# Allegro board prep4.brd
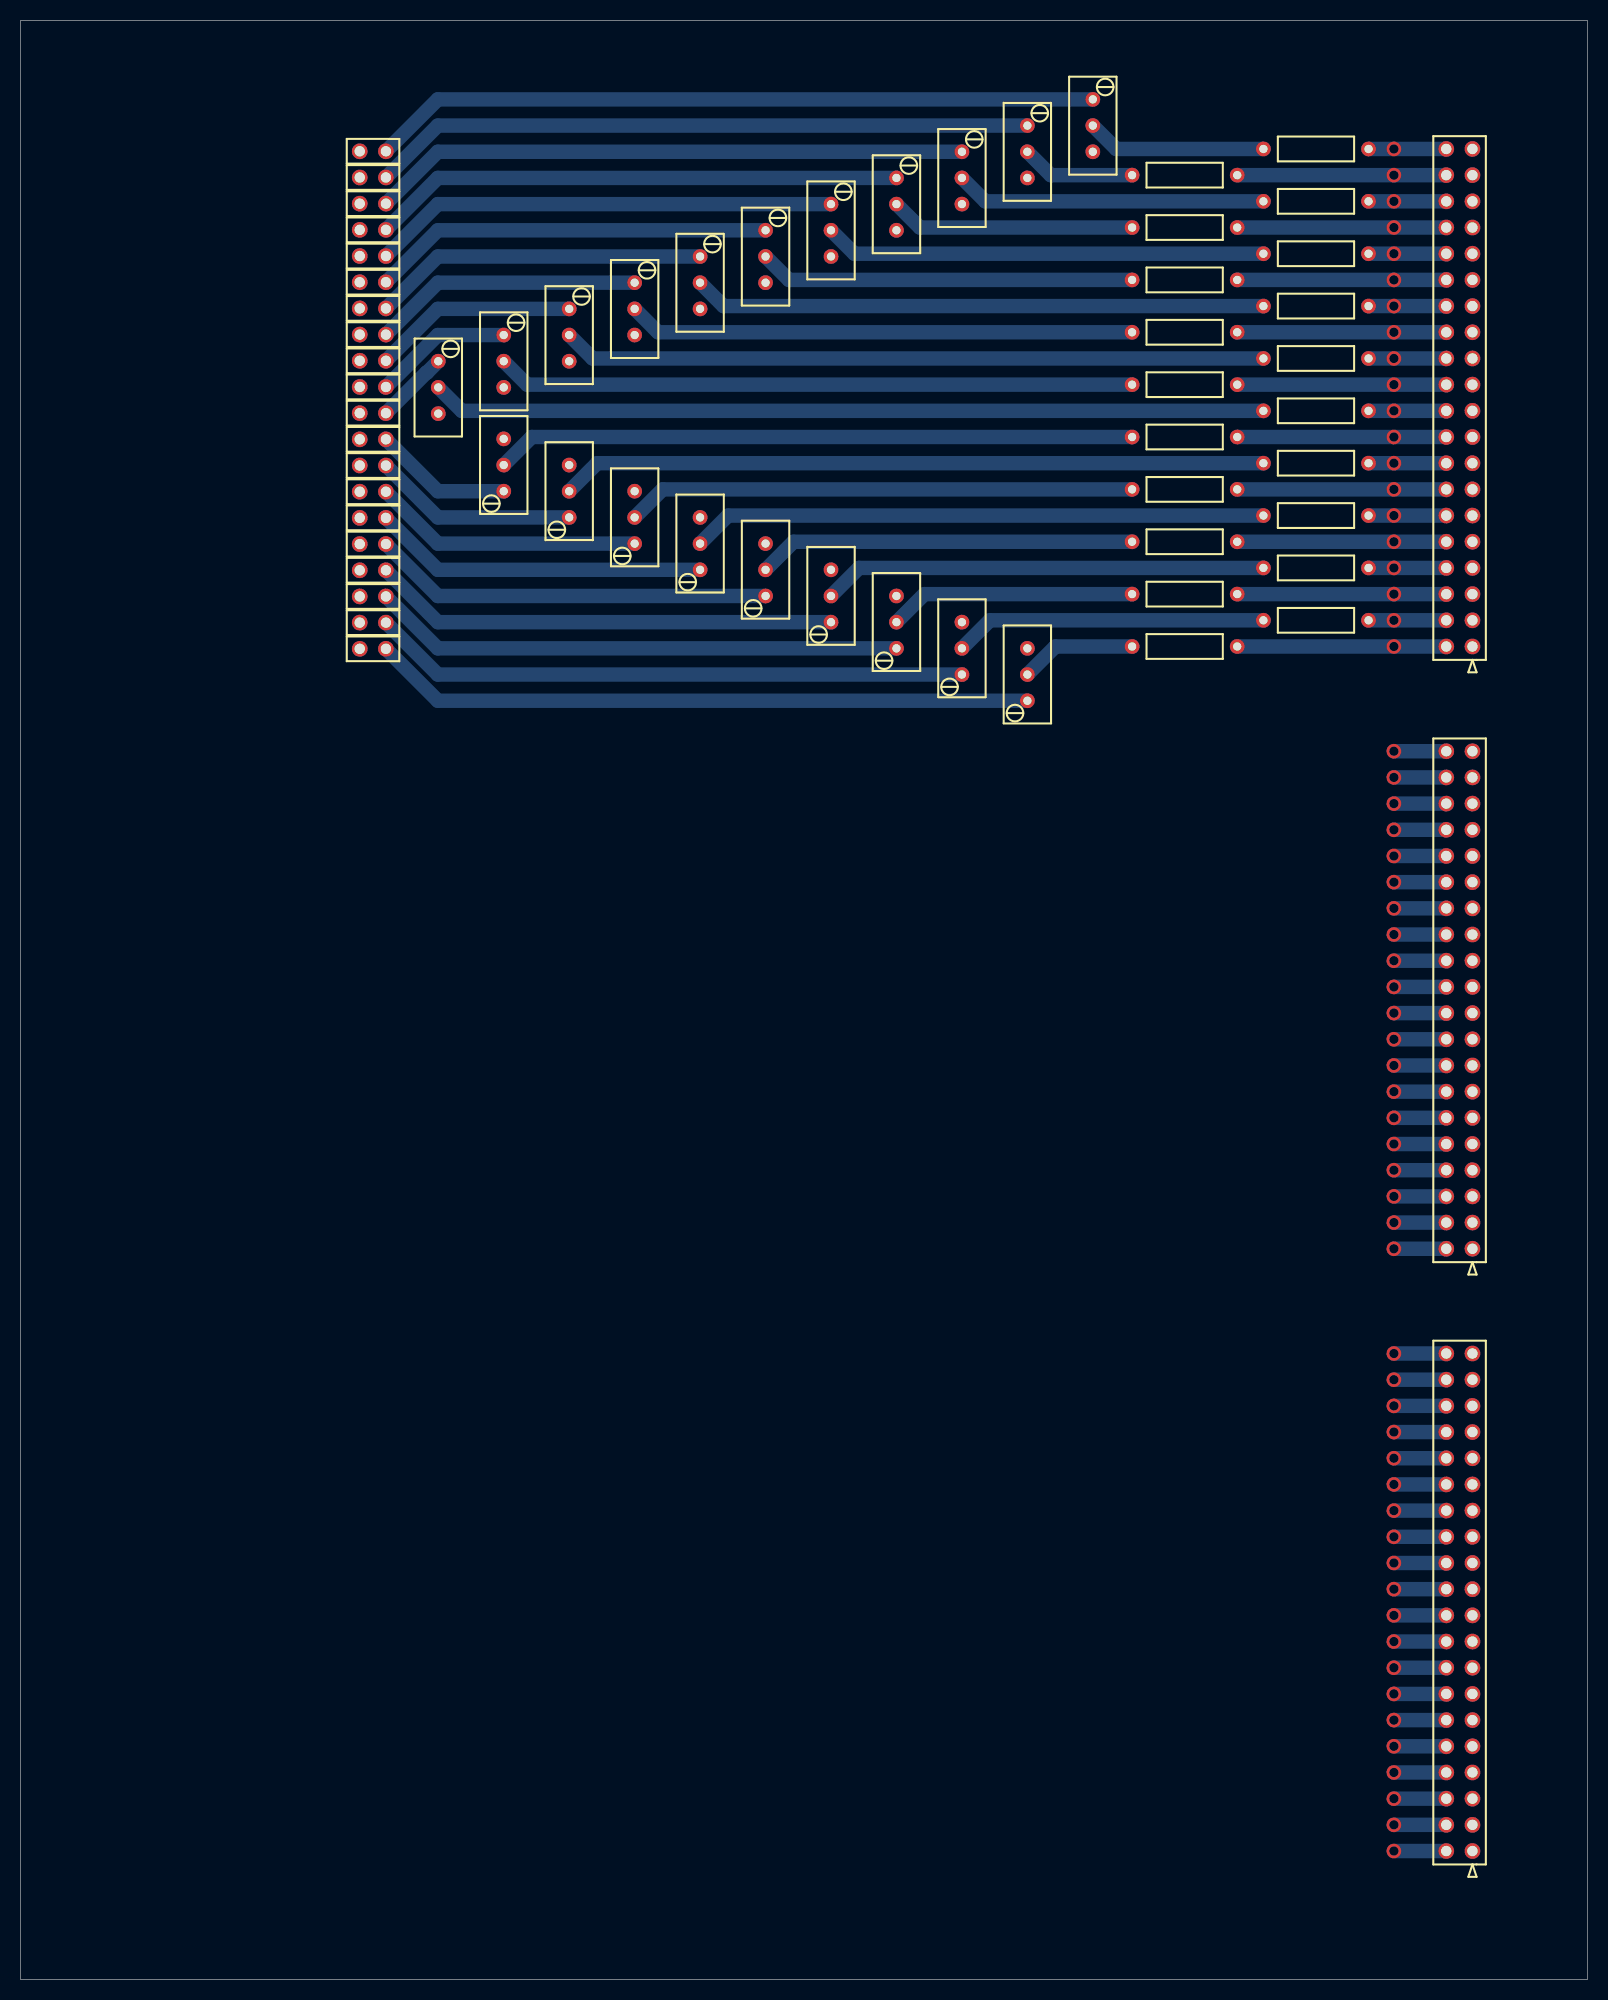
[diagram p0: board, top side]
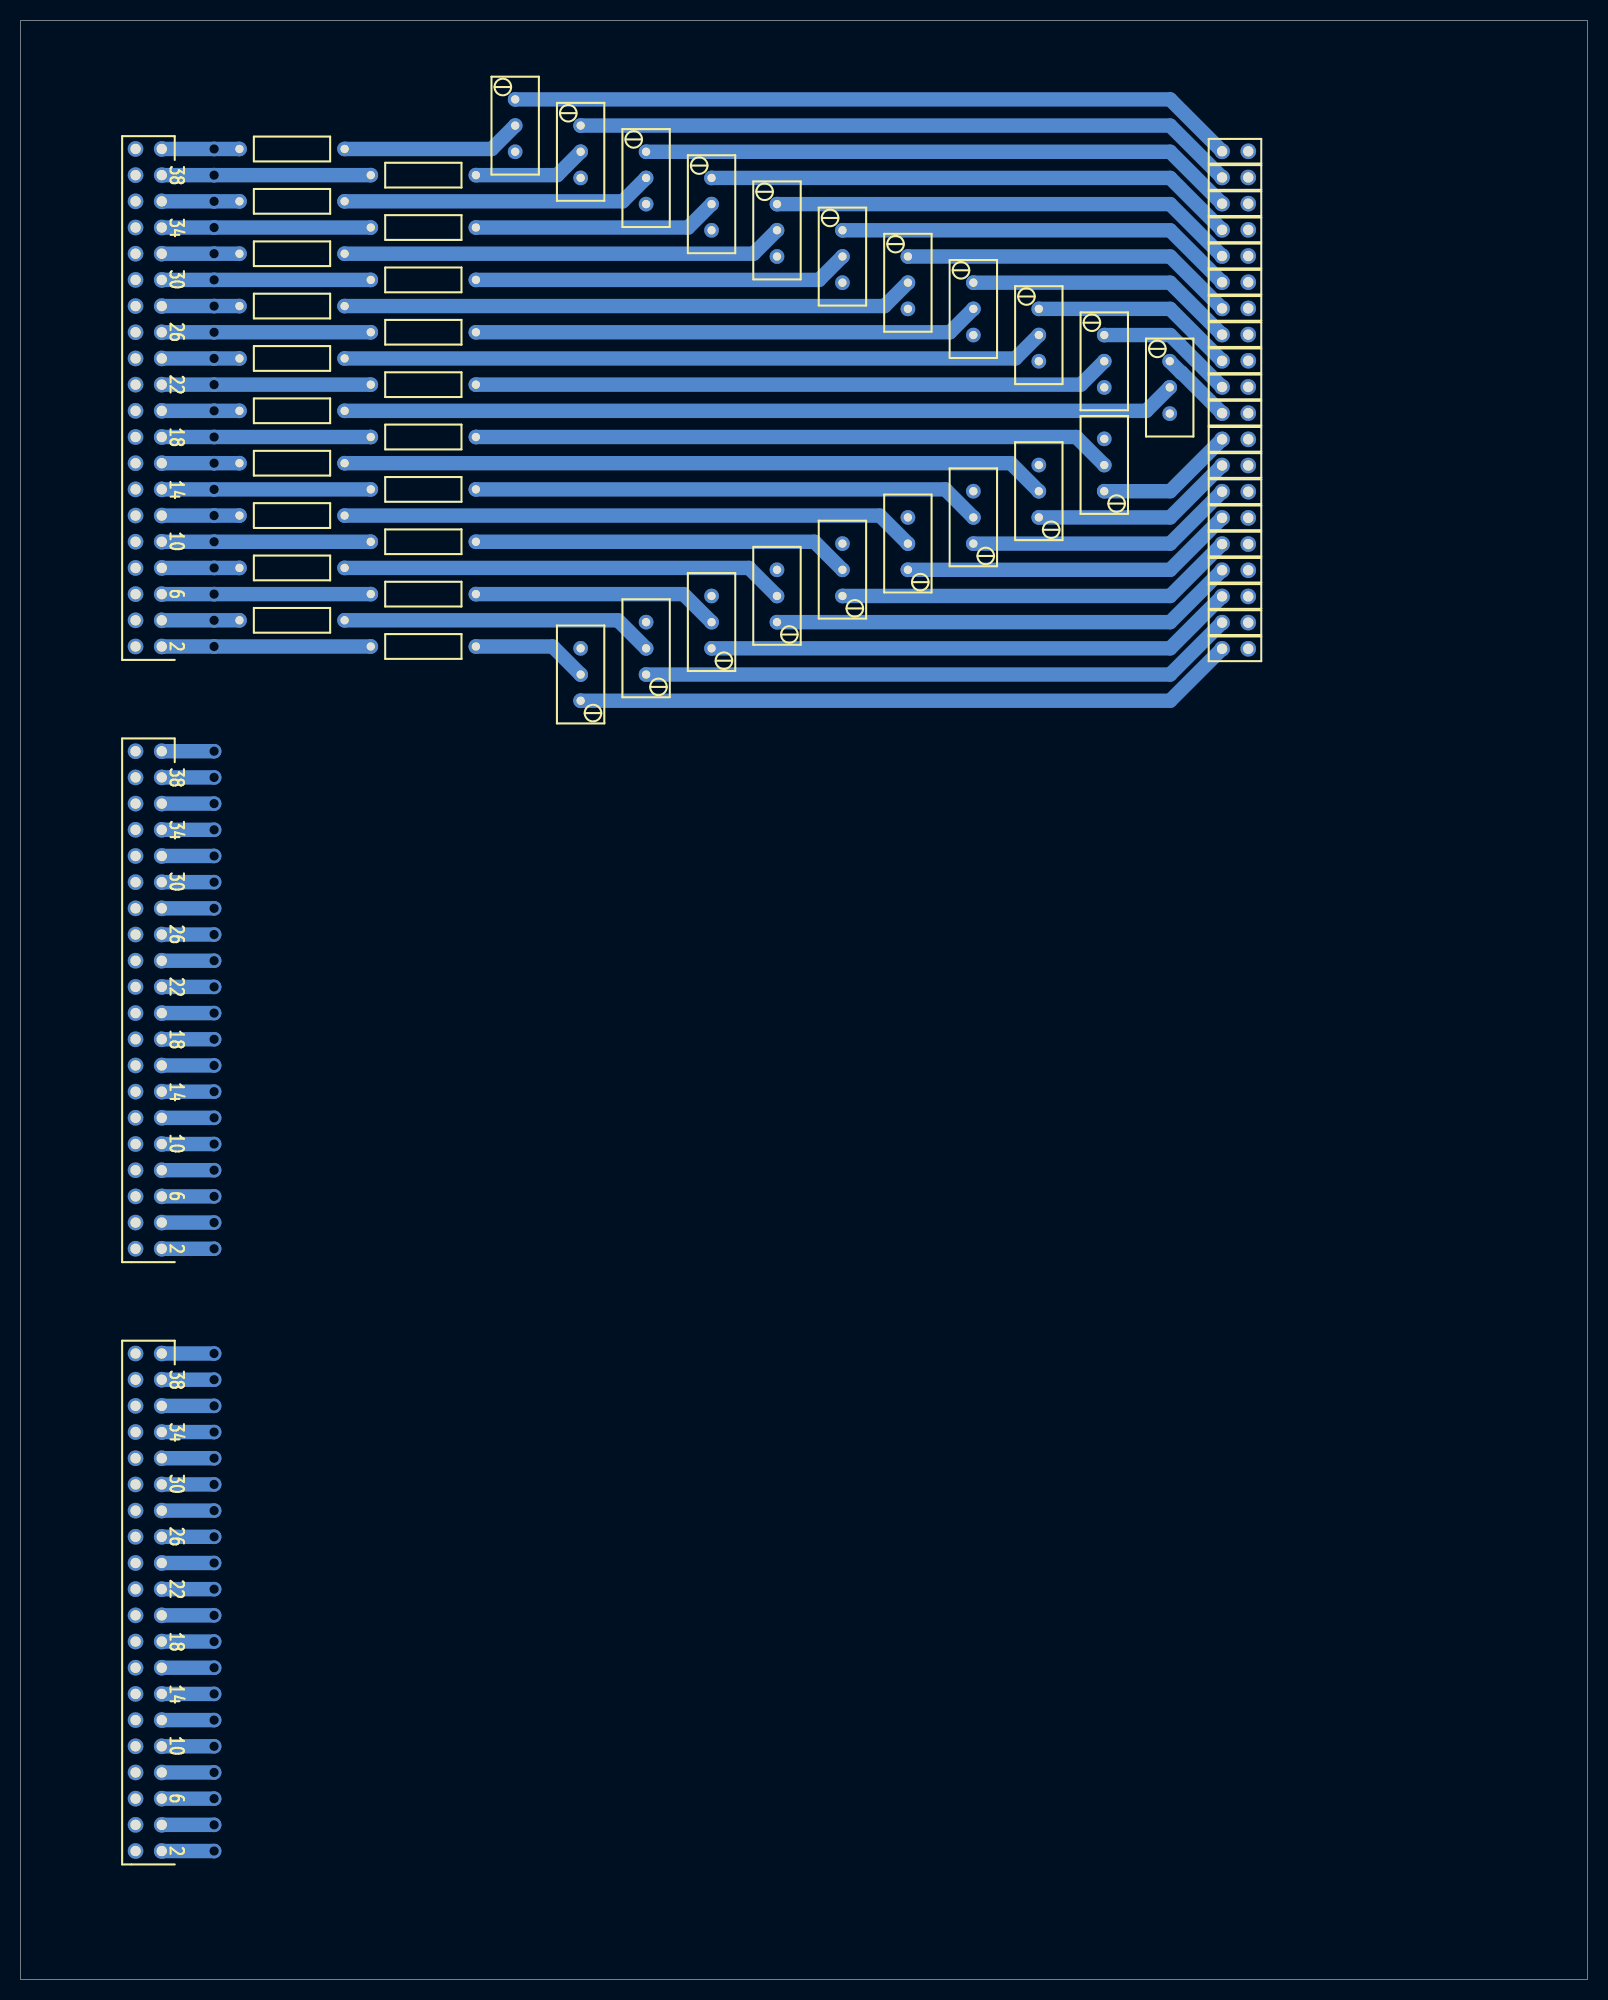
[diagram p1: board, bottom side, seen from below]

Outline 152 x 190 mm; copper layers: TOP, BOTTOM. Coordinates in mm from the lower left corner of the outline.
Outline path: 0,190 152,190 152,0 0,0 0,190

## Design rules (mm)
constraint set DEFAULT: min track width 0.15, pair gap 0.15

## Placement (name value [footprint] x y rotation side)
J1  -  [CONHE13D2X20M]  140.85 129.29 0 top
J2  -  [CONHE13D2X20M]  140.85 70.87 0 top
J3  -  [CONHE13D2X20M]  140.85 12.45 0 top
NOREF  -  []  0 0 90 top
NOREF#2  -  []  0 0 0 top
PO1  100  [POT45X95D]  104.02 182.36 270 top
PO2  100  [POT45X95D]  97.67 179.82 270 top
PO3  100  [POT45X95D]  91.32 177.28 270 top
PO4  100  [POT45X95D]  84.97 174.74 270 top
PO5  100  [POT45X95D]  78.62 172.2 270 top
PO6  100  [POT45X95D]  72.27 169.66 270 top
PO7  100  [POT45X95D]  65.92 167.12 270 top
PO8  100  [POT45X95D]  59.57 164.58 270 top
PO9  100  [POT45X95D]  53.22 162.04 270 top
PO10  100  [POT45X95D]  46.87 159.5 270 top
PO11  100  [POT45X95D]  40.52 156.96 270 top
PO12  100  [POT45X95D]  46.87 144.35 90 top
PO13  100  [POT45X95D]  53.22 141.81 90 top
PO14  100  [POT45X95D]  59.57 139.27 90 top
PO15  100  [POT45X95D]  65.92 136.73 90 top
PO16  100  [POT45X95D]  72.27 134.19 90 top
PO17  100  [POT45X95D]  78.62 131.65 90 top
PO18  100  [POT45X95D]  84.97 129.11 90 top
PO19  100  [POT45X95D]  91.32 126.57 90 top
PO20  100  [POT45X95D]  97.67 124.03 90 top
R1  100  [R100]  130.77 177.55 180 top
R2  100  [R100]  118.03 175.01 180 top
R3  100  [R100]  130.77 172.47 180 top
R4  100  [R100]  118.03 169.93 180 top
R5  100  [R100]  130.77 167.39 180 top
R6  100  [R100]  118.03 164.85 180 top
R7  100  [R100]  130.77 162.31 180 top
R8  100  [R100]  118.03 159.77 180 top
R9  100  [R100]  130.77 157.23 180 top
R10  100  [R100]  118.03 154.69 180 top
R11  100  [R100]  130.77 152.15 180 top
R12  100  [R100]  118.03 149.61 180 top
R13  100  [R100]  130.77 147.07 180 top
R14  100  [R100]  118.03 144.53 180 top
R15  100  [R100]  130.77 141.99 180 top
R16  100  [R100]  118.03 139.45 180 top
R17  100  [R100]  130.77 136.91 180 top
R18  100  [R100]  118.03 134.37 180 top
R19  100  [R100]  130.77 131.83 180 top
R20  100  [R100]  118.03 129.29 180 top
S1  -  [CONHE13D2M]  35.44 177.32 180 top
S2  -  [CONHE13D2M]  35.44 174.78 180 top
S3  -  [CONHE13D2M]  35.44 172.25 180 top
S4  -  [CONHE13D2M]  35.44 169.71 180 top
S5  -  [CONHE13D2M]  35.44 167.16 180 top
S6  -  [CONHE13D2M]  35.44 164.62 180 top
S7  -  [CONHE13D2M]  35.44 162.09 180 top
S8  -  [CONHE13D2M]  35.44 159.54 180 top
S9  -  [CONHE13D2M]  35.44 157 180 top
S10  -  [CONHE13D2M]  35.44 154.47 180 top
S11  -  [CONHE13D2M]  35.44 151.93 180 top
S12  -  [CONHE13D2M]  35.44 149.38 180 top
S13  -  [CONHE13D2M]  35.44 146.84 180 top
S14  -  [CONHE13D2M]  35.44 144.31 180 top
S15  -  [CONHE13D2M]  35.44 141.76 180 top
S16  -  [CONHE13D2M]  35.44 139.22 180 top
S17  -  [CONHE13D2M]  35.44 136.69 180 top
S18  -  [CONHE13D2M]  35.44 134.15 180 top
S19  -  [CONHE13D2M]  35.44 131.6 180 top
S20  -  [CONHE13D2M]  35.44 129.06 180 top

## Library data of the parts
J1-J3 = CON40P: part number: CON40P-HE13D
PO1-PO20 = POT: part number: POT-100,1/2W20T_D
R1-R20 = RGEN: part number: RGEN-100,M500MW5%
S1-S20 = STRAP: part number: STRAP-2X1

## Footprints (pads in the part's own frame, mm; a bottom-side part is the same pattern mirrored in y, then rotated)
CONHE13D2M
  round 1.52 hole 1: 1(0,0) 2(2.54,0)
CONHE13D2X20M
  round 1.52 hole 1: 1(0,0) 2(-2.54,0) 3(0,2.54) 4(-2.54,2.54) 5(0,5.08) 6(-2.54,5.08) 7(0,7.62) 8(-2.54,7.62) 9(0,10.16) 10(-2.54,10.16) 11(0,12.7) 12(-2.54,12.7) 13(0,15.24) 14(-2.54,15.24) 15(0,17.78) 16(-2.54,17.78) 17(0,20.32) 18(-2.54,20.32) 19(0,22.86) 20(-2.54,22.86) 21(0,25.4) 22(-2.54,25.4) 23(0,27.94) 24(-2.54,27.94) 25(0,30.48) 26(-2.54,30.48) 27(0,33.02) 28(-2.54,33.02) 29(0,35.56) 30(-2.54,35.56) 31(0,38.1) 32(-2.54,38.1) 33(0,40.64) 34(-2.54,40.64) 35(0,43.18) 36(-2.54,43.18) 37(0,45.72) 38(-2.54,45.72) 39(0,48.26) 40(-2.54,48.26)
POT45X95D
  round 1.43 hole 0.8: 1(0,0) 2(2.54,0) 3(5.08,0)
R100
  round 1.43 hole 0.8: 1(0,0) 2(10.2,0)

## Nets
GND: J1.1 J1.3 J1.5 J1.7 J1.9 J1.11 J1.13 J1.15 J1.17 J1.19 J1.21 J1.23 J1.25 J1.27 J1.29 J1.31 J1.33 J1.35 J1.37 J1.39 J2.1 J2.3 J2.5 J2.7 J2.9 J2.11 J2.13 J2.15 J2.17 J2.19 J2.21 J2.23 J2.25 J2.27 J2.29 J2.31 J2.33 J2.35 J2.37 J2.39 J3.1 J3.3 J3.5 J3.7 J3.9 J3.11 J3.13 J3.15 J3.17 J3.19 J3.21 J3.23 J3.25 J3.27 J3.29 J3.31 J3.33 J3.35 J3.37 J3.39
UNNAMED_1_CON40P_I1_A: J1.10(A<9>) R16.1
UNNAMED_1_CON40P_I1_A_1: J1.8 R17.1
UNNAMED_1_CON40P_I1_A_2: J1.6 R18.1
UNNAMED_1_CON40P_I1_A_3: J1.4 R19.1
UNNAMED_1_CON40P_I1_A_4: J1.40 R1.1
UNNAMED_1_CON40P_I1_A_5: J1.38 R2.1
UNNAMED_1_CON40P_I1_A_6: J1.36 R3.1
UNNAMED_1_CON40P_I1_A_7: J1.34 R4.1
UNNAMED_1_CON40P_I1_A_8: J1.32 R5.1
UNNAMED_1_CON40P_I1_A_9: J1.30 R6.1
UNNAMED_1_CON40P_I1_A_10: J1.28 R7.1
UNNAMED_1_CON40P_I1_A_11: J1.26 R8.1
UNNAMED_1_CON40P_I1_A_12: J1.24 R9.1
UNNAMED_1_CON40P_I1_A_13: J1.22 R10.1
UNNAMED_1_CON40P_I1_A_14: J1.2 R20.1
UNNAMED_1_CON40P_I1_A_15: J1.20 R11.1
UNNAMED_1_CON40P_I1_A_16: J1.18 R12.1
UNNAMED_1_CON40P_I1_A_17: J1.16 R13.1
UNNAMED_1_CON40P_I1_A_18: J1.14 R14.1
UNNAMED_1_CON40P_I1_A_19: J1.12 R15.1
UNNAMED_1_CON40P_I2_A: J2.28
UNNAMED_1_CON40P_I2_A_1: J2.30
UNNAMED_1_CON40P_I2_A_2: J2.38
UNNAMED_1_CON40P_I2_A_3: J2.32
UNNAMED_1_CON40P_I2_A_4: J2.34
UNNAMED_1_CON40P_I2_A_5: J2.36
UNNAMED_1_CON40P_I2_A_6: J2.40
UNNAMED_1_CON40P_I2_A_7: J2.6
UNNAMED_1_CON40P_I2_A_8: J2.8
UNNAMED_1_CON40P_I2_A_9: J2.4
UNNAMED_1_CON40P_I2_A_10: J2.2
UNNAMED_1_CON40P_I2_A_11: J2.10(A<9>)
UNNAMED_1_CON40P_I2_A_12: J2.12
UNNAMED_1_CON40P_I2_A_13: J2.14
UNNAMED_1_CON40P_I2_A_14: J2.16
UNNAMED_1_CON40P_I2_A_15: J2.18
UNNAMED_1_CON40P_I2_A_16: J2.20
UNNAMED_1_CON40P_I2_A_17: J2.22
UNNAMED_1_CON40P_I2_A_18: J2.24
UNNAMED_1_CON40P_I2_A_19: J2.26
UNNAMED_1_CON40P_I3_A: J3.28
UNNAMED_1_CON40P_I3_A_1: J3.30
UNNAMED_1_CON40P_I3_A_2: J3.38
UNNAMED_1_CON40P_I3_A_3: J3.32
UNNAMED_1_CON40P_I3_A_4: J3.34
UNNAMED_1_CON40P_I3_A_5: J3.36
UNNAMED_1_CON40P_I3_A_6: J3.40
UNNAMED_1_CON40P_I3_A_7: J3.6
UNNAMED_1_CON40P_I3_A_8: J3.8
UNNAMED_1_CON40P_I3_A_9: J3.4
UNNAMED_1_CON40P_I3_A_10: J3.2
UNNAMED_1_CON40P_I3_A_11: J3.10(A<9>)
UNNAMED_1_CON40P_I3_A_12: J3.12
UNNAMED_1_CON40P_I3_A_13: J3.14
UNNAMED_1_CON40P_I3_A_14: J3.16
UNNAMED_1_CON40P_I3_A_15: J3.18
UNNAMED_1_CON40P_I3_A_16: J3.20
UNNAMED_1_CON40P_I3_A_17: J3.22
UNNAMED_1_CON40P_I3_A_18: J3.24
UNNAMED_1_CON40P_I3_A_19: J3.26
UNNAMED_1_POT_I5_A: PO1.1 S1.1
UNNAMED_1_POT_I5_B: PO1.2 R1.2(B<0>)
UNNAMED_1_POT_I7_A: PO2.1 S2.1
UNNAMED_1_POT_I7_B: PO2.2 R2.2(B<0>)
UNNAMED_1_POT_I26_A: PO3.1 S3.1
UNNAMED_1_POT_I26_B: PO3.2 R3.2(B<0>)
UNNAMED_1_POT_I27_A: PO4.1 S4.1
UNNAMED_1_POT_I27_B: PO4.2 R4.2(B<0>)
UNNAMED_1_POT_I28_A: PO5.1 S5.1
UNNAMED_1_POT_I28_B: PO5.2 R5.2(B<0>)
UNNAMED_1_POT_I29_A: PO6.1 S6.1
UNNAMED_1_POT_I29_B: PO6.2 R6.2(B<0>)
UNNAMED_1_POT_I30_A: PO7.1 S7.1
UNNAMED_1_POT_I30_B: PO7.2 R7.2(B<0>)
UNNAMED_1_POT_I31_A: PO8.1 S8.1
UNNAMED_1_POT_I31_B: PO8.2 R8.2(B<0>)
UNNAMED_1_POT_I32_A: PO9.1 S9.1
UNNAMED_1_POT_I32_B: PO9.2 R9.2(B<0>)
UNNAMED_1_POT_I33_A: PO10.1 S10.1
UNNAMED_1_POT_I33_B: PO10.2 R10.2(B<0>)
UNNAMED_1_POT_I34_A: PO11.1 S11.1
UNNAMED_1_POT_I34_B: PO11.2 R11.2(B<0>)
UNNAMED_1_POT_I35_A: PO12.1 S12.1
UNNAMED_1_POT_I35_B: PO12.2 R12.2(B<0>)
UNNAMED_1_POT_I36_A: PO13.1 S13.1
UNNAMED_1_POT_I36_B: PO13.2 R13.2(B<0>)
UNNAMED_1_POT_I37_A: PO14.1 S14.1
UNNAMED_1_POT_I37_B: PO14.2 R14.2(B<0>)
UNNAMED_1_POT_I38_A: PO15.1 S15.1
UNNAMED_1_POT_I38_B: PO15.2 R15.2(B<0>)
UNNAMED_1_POT_I39_A: PO16.1 S16.1
UNNAMED_1_POT_I39_B: PO16.2 R16.2(B<0>)
UNNAMED_1_POT_I40_A: PO17.1 S17.1
UNNAMED_1_POT_I40_B: PO17.2 R17.2(B<0>)
UNNAMED_1_POT_I41_A: PO18.1 S18.1
UNNAMED_1_POT_I41_B: PO18.2 R18.2(B<0>)
UNNAMED_1_POT_I42_A: PO19.1 S19.1
UNNAMED_1_POT_I42_B: PO19.2 R19.2(B<0>)
UNNAMED_1_POT_I43_A: PO20.1 S20.1
UNNAMED_1_POT_I43_B: PO20.2 R20.2(B<0>)
UNNAMED_1_STRAP_I125_B: S1.2(B) S2.2(B) S3.2(B) S4.2(B) S5.2(B) S6.2(B) S7.2(B) S8.2(B) S9.2(B) S10.2(B) S11.2(B) S12.2(B) S13.2(B) S14.2(B) S15.2(B) S16.2(B) S17.2(B) S18.2(B) S19.2(B) S20.2(B)

Pads without a net: PO1 3; PO2 3; PO3 3; PO4 3; PO5 3; PO6 3; PO7 3; PO8 3; PO9 3; PO10 3; PO11 3; PO12 3; PO13 3; PO14 3; PO15 3; PO16 3; PO17 3; PO18 3; PO19 3; PO20 3

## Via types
v1: diameter 1.42, hole 0.9, TOP to BOTTOM, 60 vias

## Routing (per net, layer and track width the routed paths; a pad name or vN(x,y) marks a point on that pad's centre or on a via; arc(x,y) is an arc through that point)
UNNAMED_1_CON40P_I1_A: length 20.3
  BOTTOM w1.4: J1.10 v1(133.23,139.45) R16.1
UNNAMED_1_CON40P_I1_A_1: length 7.5
  BOTTOM w1.4: R17.1 v1(133.23,136.91) J1.8
UNNAMED_1_CON40P_I1_A_2: length 20.3
  BOTTOM w1.4: R18.1 v1(133.23,134.37) J1.6
UNNAMED_1_CON40P_I1_A_3: length 7.5
  BOTTOM w1.4: J1.4 v1(133.23,131.83) R19.1
UNNAMED_1_CON40P_I1_A_4: length 7.5
  BOTTOM w1.4: J1.40 v1(133.23,177.55) R1.1
UNNAMED_1_CON40P_I1_A_5: length 20.3
  BOTTOM w1.4: J1.38 v1(133.23,175.01) R2.1
UNNAMED_1_CON40P_I1_A_6: length 7.5
  BOTTOM w1.4: J1.36 v1(133.23,172.47) R3.1
UNNAMED_1_CON40P_I1_A_7: length 20.3
  BOTTOM w1.4: R4.1 v1(133.23,169.93) J1.34
UNNAMED_1_CON40P_I1_A_8: length 7.5
  BOTTOM w1.4: J1.32 v1(133.23,167.39) R5.1
UNNAMED_1_CON40P_I1_A_9: length 20.3
  BOTTOM w1.4: J1.30 v1(133.23,164.85) R6.1
UNNAMED_1_CON40P_I1_A_10: length 7.5
  BOTTOM w1.4: R7.1 v1(133.23,162.31) J1.28
UNNAMED_1_CON40P_I1_A_11: length 20.3
  BOTTOM w1.4: J1.26 v1(133.23,159.77) R8.1
UNNAMED_1_CON40P_I1_A_12: length 7.5
  BOTTOM w1.4: R9.1 v1(133.23,157.23) J1.24
UNNAMED_1_CON40P_I1_A_13: length 20.3
  BOTTOM w1.4: J1.22 v1(133.23,154.69) R10.1
UNNAMED_1_CON40P_I1_A_14: length 20.3
  BOTTOM w1.4: R20.1 v1(133.23,129.29) J1.2
UNNAMED_1_CON40P_I1_A_15: length 7.5
  BOTTOM w1.4: R11.1 v1(133.23,152.15) J1.20
UNNAMED_1_CON40P_I1_A_16: length 20.3
  BOTTOM w1.4: J1.18 v1(133.23,149.61) R12.1
UNNAMED_1_CON40P_I1_A_17: length 7.5
  BOTTOM w1.4: R13.1 v1(133.23,147.07) J1.16
UNNAMED_1_CON40P_I1_A_18: length 20.3
  BOTTOM w1.4: J1.14 v1(133.23,144.53) R14.1
UNNAMED_1_CON40P_I1_A_19: length 7.5
  BOTTOM w1.4: J1.12 v1(133.23,141.99) R15.1
UNNAMED_1_CON40P_I2_A: length 5.1
  BOTTOM w1.4: J2.28 v1(133.23,103.89)
UNNAMED_1_CON40P_I2_A_1: length 5.1
  BOTTOM w1.4: J2.30 v1(133.23,106.43)
UNNAMED_1_CON40P_I2_A_2: length 5.1
  BOTTOM w1.4: J2.38 v1(133.23,116.59)
UNNAMED_1_CON40P_I2_A_3: length 5.1
  BOTTOM w1.4: J2.32 v1(133.23,108.97)
UNNAMED_1_CON40P_I2_A_4: length 5.1
  BOTTOM w1.4: J2.34 v1(133.23,111.51)
UNNAMED_1_CON40P_I2_A_5: length 5.1
  BOTTOM w1.4: J2.36 v1(133.23,114.05)
UNNAMED_1_CON40P_I2_A_6: length 5.1
  BOTTOM w1.4: J2.40 v1(133.23,119.13)
UNNAMED_1_CON40P_I2_A_7: length 5.1
  BOTTOM w1.4: J2.6 v1(133.23,75.95)
UNNAMED_1_CON40P_I2_A_8: length 5.1
  BOTTOM w1.4: J2.8 v1(133.23,78.49)
UNNAMED_1_CON40P_I2_A_9: length 5.1
  BOTTOM w1.4: J2.4 v1(133.23,73.41)
UNNAMED_1_CON40P_I2_A_10: length 5.1
  BOTTOM w1.4: J2.2 v1(133.23,70.87)
UNNAMED_1_CON40P_I2_A_11: length 5.1
  BOTTOM w1.4: J2.10 v1(133.23,81.03)
UNNAMED_1_CON40P_I2_A_12: length 5.1
  BOTTOM w1.4: J2.12 v1(133.23,83.57)
UNNAMED_1_CON40P_I2_A_13: length 5.1
  BOTTOM w1.4: J2.14 v1(133.23,86.11)
UNNAMED_1_CON40P_I2_A_14: length 5.1
  BOTTOM w1.4: J2.16 v1(133.23,88.65)
UNNAMED_1_CON40P_I2_A_15: length 5.1
  BOTTOM w1.4: J2.18 v1(133.23,91.19)
UNNAMED_1_CON40P_I2_A_16: length 5.1
  BOTTOM w1.4: J2.20 v1(133.23,93.73)
UNNAMED_1_CON40P_I2_A_17: length 5.1
  BOTTOM w1.4: J2.22 v1(133.23,96.27)
UNNAMED_1_CON40P_I2_A_18: length 5.1
  BOTTOM w1.4: J2.24 v1(133.23,98.81)
UNNAMED_1_CON40P_I2_A_19: length 5.1
  BOTTOM w1.4: J2.26 v1(133.23,101.35)
UNNAMED_1_CON40P_I3_A: length 5.1
  BOTTOM w1.4: J3.28 v1(133.23,45.47)
UNNAMED_1_CON40P_I3_A_1: length 5.1
  BOTTOM w1.4: J3.30 v1(133.23,48.01)
UNNAMED_1_CON40P_I3_A_2: length 5.1
  BOTTOM w1.4: J3.38 v1(133.23,58.17)
UNNAMED_1_CON40P_I3_A_3: length 5.1
  BOTTOM w1.4: J3.32 v1(133.23,50.55)
UNNAMED_1_CON40P_I3_A_4: length 5.1
  BOTTOM w1.4: J3.34 v1(133.23,53.09)
UNNAMED_1_CON40P_I3_A_5: length 5.1
  BOTTOM w1.4: J3.36 v1(133.23,55.63)
UNNAMED_1_CON40P_I3_A_6: length 5.1
  BOTTOM w1.4: J3.40 v1(133.23,60.71)
UNNAMED_1_CON40P_I3_A_7: length 5.1
  BOTTOM w1.4: J3.6 v1(133.23,17.53)
UNNAMED_1_CON40P_I3_A_8: length 5.1
  BOTTOM w1.4: J3.8 v1(133.23,20.07)
UNNAMED_1_CON40P_I3_A_9: length 5.1
  BOTTOM w1.4: J3.4 v1(133.23,14.99)
UNNAMED_1_CON40P_I3_A_10: length 5.1
  BOTTOM w1.4: J3.2 v1(133.23,12.45)
UNNAMED_1_CON40P_I3_A_11: length 5.1
  BOTTOM w1.4: J3.10 v1(133.23,22.61)
UNNAMED_1_CON40P_I3_A_12: length 5.1
  BOTTOM w1.4: J3.12 v1(133.23,25.15)
UNNAMED_1_CON40P_I3_A_13: length 5.1
  BOTTOM w1.4: J3.14 v1(133.23,27.69)
UNNAMED_1_CON40P_I3_A_14: length 5.1
  BOTTOM w1.4: J3.16 v1(133.23,30.23)
UNNAMED_1_CON40P_I3_A_15: length 5.1
  BOTTOM w1.4: J3.18 v1(133.23,32.77)
UNNAMED_1_CON40P_I3_A_16: length 5.1
  BOTTOM w1.4: J3.20 v1(133.23,35.31)
UNNAMED_1_CON40P_I3_A_17: length 5.1
  BOTTOM w1.4: J3.22 v1(133.23,37.85)
UNNAMED_1_CON40P_I3_A_18: length 5.1
  BOTTOM w1.4: J3.24 v1(133.23,40.39)
UNNAMED_1_CON40P_I3_A_19: length 5.1
  BOTTOM w1.4: J3.26 v1(133.23,42.93)
UNNAMED_1_POT_I5_A: length 70.7
  BOTTOM w1.4: S1.1 40.48,182.36 PO1.1
UNNAMED_1_POT_I5_B: length 17.5
  BOTTOM w1.4: PO1.2 106.29,177.55 R1.2
UNNAMED_1_POT_I7_A: length 64.3
  BOTTOM w1.4: S2.1 40.48,179.82 PO2.1
UNNAMED_1_POT_I7_B: length 11.1
  BOTTOM w1.4: R2.2 99.94,175.01 PO2.2
UNNAMED_1_POT_I26_A: length 58
  BOTTOM w1.4: S3.1 40.48,177.28 PO3.1
UNNAMED_1_POT_I26_B: length 30.2
  BOTTOM w1.4: PO3.2 93.59,172.47 R3.2
UNNAMED_1_POT_I27_A: length 51.6
  BOTTOM w1.4: PO4.1 40.48,174.74 S4.1
UNNAMED_1_POT_I27_B: length 23.8
  BOTTOM w1.4: R4.2 87.24,169.93 PO4.2
UNNAMED_1_POT_I28_A: length 45.3
  BOTTOM w1.4: S5.1 40.48,172.2 PO5.1
UNNAMED_1_POT_I28_B: length 42.9
  BOTTOM w1.4: PO5.2 80.89,167.39 R5.2
UNNAMED_1_POT_I29_A: length 38.9
  BOTTOM w1.4: S6.1 40.48,169.66 PO6.1
UNNAMED_1_POT_I29_B: length 36.5
  BOTTOM w1.4: PO6.2 74.54,164.85 R6.2
UNNAMED_1_POT_I30_A: length 32.6
  BOTTOM w1.4: PO7.1 40.48,167.12 S7.1
UNNAMED_1_POT_I30_B: length 55.6
  BOTTOM w1.4: PO7.2 68.19,162.31 R7.2
UNNAMED_1_POT_I31_A: length 26.2
  BOTTOM w1.4: PO8.1 40.48,164.58 S8.1
UNNAMED_1_POT_I31_B: length 49.2
  BOTTOM w1.4: R8.2 61.84,159.77 PO8.2
UNNAMED_1_POT_I32_A: length 19.9
  BOTTOM w1.4: S9.1 40.48,162.04 PO9.1
UNNAMED_1_POT_I32_B: length 68.3
  BOTTOM w1.4: PO9.2 55.49,157.23 R9.2
UNNAMED_1_POT_I33_A: length 13.5
  BOTTOM w1.4: PO10.1 40.48,159.5 S10.1
UNNAMED_1_POT_I33_B: length 61.9
  BOTTOM w1.4: R10.2 49.14,154.69 PO10.2
UNNAMED_1_POT_I34_A: length 7.2
  BOTTOM w1.4: PO11.1 39.41,155.85 39.37,155.85 S11.1
UNNAMED_1_POT_I34_B: length 81
  BOTTOM w1.4: PO11.2 42.79,152.15 R11.2
UNNAMED_1_POT_I35_A: length 13.5
  BOTTOM w1.4: PO12.1 40.48,144.35 S12.1
UNNAMED_1_POT_I35_B: length 62.1
  BOTTOM w1.4: PO12.2 49.59,149.61 R12.2
UNNAMED_1_POT_I36_A: length 19.9
  BOTTOM w1.4: PO13.1 40.48,141.81 S13.1
UNNAMED_1_POT_I36_B: length 68.5
  BOTTOM w1.4: PO13.2 55.94,147.07 R13.2
UNNAMED_1_POT_I37_A: length 26.2
  BOTTOM w1.4: S14.1 40.48,139.27 PO14.1
UNNAMED_1_POT_I37_B: length 49.4
  BOTTOM w1.4: PO14.2 62.29,144.53 R14.2
UNNAMED_1_POT_I38_A: length 32.6
  BOTTOM w1.4: PO15.1 40.48,136.73 S15.1
UNNAMED_1_POT_I38_B: length 55.8
  BOTTOM w1.4: PO15.2 68.64,141.99 R15.2
UNNAMED_1_POT_I39_A: length 38.9
  BOTTOM w1.4: PO16.1 40.48,134.19 S16.1
UNNAMED_1_POT_I39_B: length 36.7
  BOTTOM w1.4: PO16.2 74.99,139.45 R16.2
UNNAMED_1_POT_I40_A: length 45.3
  BOTTOM w1.4: PO17.1 40.48,131.65 S17.1
UNNAMED_1_POT_I40_B: length 43.1
  BOTTOM w1.4: PO17.2 81.34,136.91 R17.2
UNNAMED_1_POT_I41_A: length 51.6
  BOTTOM w1.4: S18.1 40.48,129.11 PO18.1
UNNAMED_1_POT_I41_B: length 24
  BOTTOM w1.4: PO18.2 87.69,134.37 R18.2
UNNAMED_1_POT_I42_A: length 58
  BOTTOM w1.4: S19.1 40.48,126.57 PO19.1
UNNAMED_1_POT_I42_B: length 30.4
  BOTTOM w1.4: PO19.2 94.04,131.83 R19.2
UNNAMED_1_POT_I43_A: length 64.3
  BOTTOM w1.4: S20.1 40.48,124.03 PO20.1
UNNAMED_1_POT_I43_B: length 11.3
  BOTTOM w1.4: R20.2 100.39,129.29 PO20.2
